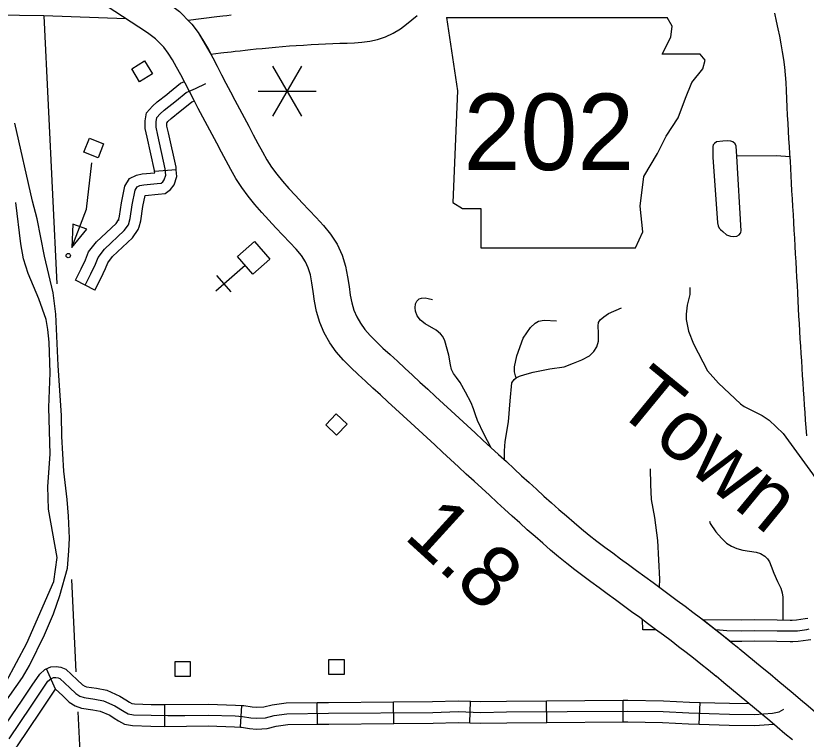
# Model space of a CAD drawing. Extents: x 1370130 to 1380143, y 377636 to 380256.
# Drawn here: x 1378334.6 to 1378563.7, y 378052.1 to 378261.9 of the extents above; entities that cross this region are included whole.
import ezdxf

# ---------------------------------------------------------------- set-up
doc = ezdxf.new("R2010")
doc.units = 0
for name, color, linetype in [('Level 10', 7, 'Continuous'), ('Level 15', 7, 'Continuous'), ('Level 21', 7, 'Continuous'), ('Level 31', 7, 'Continuous'), ('Level 32', 7, 'Continuous'), ('Level 33', 7, 'Continuous'), ('Level 34', 7, 'Continuous'), ('Level 35', 7, 'Continuous'), ('Level 4', 7, 'Continuous'), ('Level 45', 7, 'Continuous'), ('Level 48', 7, 'Continuous'), ('Level 5', 7, 'Continuous'), ('Level 56', 7, 'Continuous'), ('Level 57', 7, 'Continuous'), ('Level 6', 7, 'Continuous')]:
    doc.layers.add(name, color=color, linetype=linetype)

msp = doc.modelspace()

# ---------------------------------------------------------------- linework, layer by layer
at = {"layer": 'Level 10'}
msp.add_line((1378561.65, 378172.62), (1378561.65, 378172.6), dxfattribs=at)
for points in [[(1378554.5, 378262.65), (1378555.02, 378260.29), (1378555.54, 378258.08), (1378556, 378255.94), (1378556.41, 378253.73), (1378556.8, 378251.48), (1378557.15, 378249.24), (1378557.44, 378247.02), (1378557.66, 378244.8), (1378557.81, 378242.52), (1378557.93, 378240.2), (1378558.02, 378237.83), (1378558.11, 378235.43), (1378558.22, 378233.02), (1378558.36, 378230.67), (1378558.5, 378228.4), (1378558.64, 378226.17), (1378558.77, 378223.97), (1378558.91, 378221.81), (1378559.04, 378219.7), (1378559.15, 378217.57), (1378559.27, 378215.47), (1378559.38, 378213.32), (1378559.51, 378211.1), (1378559.64, 378208.84), (1378559.78, 378206.56), (1378559.91, 378204.24), (1378560.05, 378201.98), (1378560.18, 378199.7), (1378560.3, 378197.41), (1378560.43, 378195.11), (1378560.56, 378192.82), (1378560.69, 378190.55), (1378560.82, 378188.26), (1378560.95, 378185.97), (1378561.07, 378183.72), (1378561.2, 378181.46), (1378561.31, 378179.22), (1378561.43, 378177.01), (1378561.54, 378174.81), (1378561.65, 378172.62)], [(1378397, 378262.03), (1378395.75, 378261.89), (1378394.64, 378261.75), (1378393.74, 378261.64), (1378392.9, 378261.56), (1378384.57, 378260.55), (1378385.66, 378259.42), (1378387.43, 378257.03), (1378391.15, 378250.77)], [(1378391.15, 378250.77), (1378394.03, 378251.12), (1378394.89, 378251.2), (1378395.93, 378251.33), (1378397.02, 378251.46), (1378398.24, 378251.61), (1378399.62, 378251.77), (1378401.09, 378251.95), (1378402.63, 378252.11), (1378404.27, 378252.27), (1378406.05, 378252.43), (1378407.96, 378252.61), (1378409.93, 378252.81), (1378411.92, 378253.01), (1378413.9, 378253.2), (1378415.91, 378253.32), (1378418.03, 378253.42), (1378420.19, 378253.52), (1378422.31, 378253.64), (1378424.39, 378253.74), (1378426.49, 378253.82), (1378428.58, 378253.92), (1378430.65, 378253.99), (1378432.75, 378254.08), (1378434.94, 378254.24), (1378437.19, 378254.55), (1378439.48, 378255.06), (1378441.77, 378255.82), (1378444, 378256.85), (1378446.09, 378258.11), (1378447.89, 378259.47), (1378449.45, 378260.74), (1378450.94, 378261.99)], [(1378561.65, 378172.6), (1378561.78, 378170.43), (1378561.9, 378168.24), (1378562.04, 378166.06), (1378562.19, 378163.92), (1378562.33, 378161.8), (1378562.46, 378159.68), (1378562.59, 378157.54), (1378562.73, 378155.42), (1378562.87, 378153.26), (1378563.01, 378151.09), (1378563.16, 378148.94), (1378563.31, 378146.79), (1378563.45, 378144.63), (1378563.59, 378142.44), (1378563.79, 378140.08)]]:
    msp.add_lwpolyline(points, dxfattribs=at)
at = {"layer": 'Level 15'}
for points in [[(1378332.91, 378293.69), (1378334.71, 378292.37), (1378336.92, 378291.04), (1378366.32, 378273.69), (1378378.87, 378265.56), (1378382.04, 378263.09), (1378385.25, 378259.87)], [(1378377.43, 378252.86), (1378375.07, 378255.22), (1378372.78, 378256.99), (1378360.8, 378264.76), (1378331.53, 378282.03)], [(1378385.25, 378259.87), (1378385.66, 378259.42), (1378387.43, 378257.03), (1378389.03, 378254.57), (1378390.42, 378252.1), (1378391.72, 378249.69), (1378393.01, 378247.25), (1378394.27, 378244.81), (1378395.54, 378242.35), (1378396.82, 378239.88), (1378398.12, 378237.39), (1378399.44, 378234.88), (1378400.77, 378232.35), (1378402.12, 378229.83), (1378403.45, 378227.32), (1378404.79, 378224.84), (1378406.12, 378222.43), (1378407.42, 378220.14), (1378408.77, 378218.02), (1378410.28, 378215.98), (1378411.95, 378213.93), (1378413.77, 378211.84), (1378415.68, 378209.72), (1378417.64, 378207.61), (1378419.65, 378205.5), (1378421.72, 378203.34), (1378423.81, 378201.06), (1378425.88, 378198.54), (1378427.77, 378195.66), (1378429.24, 378192.47), (1378430.2, 378189.26), (1378430.79, 378186.21), (1378431.21, 378183.4), (1378431.58, 378180.85), (1378432.02, 378178.59), (1378432.63, 378176.53), (1378433.47, 378174.56), (1378434.51, 378172.69), (1378435.79, 378170.9), (1378437.3, 378169.15), (1378439.06, 378167.38), (1378441.03, 378165.53), (1378443.09, 378163.62), (1378445.22, 378161.67), (1378447.37, 378159.68), (1378449.56, 378157.69), (1378451.76, 378155.66), (1378454.02, 378153.59), (1378456.29, 378151.49), (1378458.57, 378149.38), (1378460.85, 378147.27), (1378463.15, 378145.15), (1378465.46, 378143.02), (1378467.74, 378140.9), (1378470.01, 378138.8), (1378472.27, 378136.72), (1378474.55, 378134.65), (1378476.81, 378132.57), (1378479.03, 378130.52), (1378481.21, 378128.5), (1378483.39, 378126.52), (1378485.54, 378124.55), (1378487.7, 378122.6), (1378489.87, 378120.66), (1378492.05, 378118.73), (1378494.25, 378116.81), (1378496.45, 378114.91), (1378498.64, 378113.06), (1378500.84, 378111.27), (1378503.07, 378109.53), (1378505.35, 378107.8), (1378507.63, 378106.08), (1378509.91, 378104.38), (1378512.22, 378102.69), (1378514.57, 378100.99), (1378516.95, 378099.26), (1378519.34, 378097.52), (1378521.71, 378095.78), (1378524.04, 378094.04), (1378526.33, 378092.32), (1378528.62, 378090.63), (1378530.89, 378088.94), (1378533.13, 378087.25), (1378535.35, 378085.54), (1378537.55, 378083.82), (1378539.78, 378082.05), (1378542.01, 378080.23), (1378544.23, 378078.43)], [(1378537.62, 378070.27), (1378535.38, 378072.09), (1378533.2, 378073.87), (1378531.05, 378075.57), (1378528.9, 378077.25), (1378526.76, 378078.9), (1378524.58, 378080.55), (1378522.36, 378082.21), (1378520.07, 378083.9), (1378517.76, 378085.62), (1378515.46, 378087.34), (1378513.13, 378089.05), (1378510.78, 378090.77), (1378508.41, 378092.49), (1378506.04, 378094.2), (1378503.67, 378095.93), (1378501.33, 378097.68), (1378499.01, 378099.43), (1378496.67, 378101.21), (1378494.3, 378103.05), (1378491.95, 378104.97), (1378489.63, 378106.92), (1378487.36, 378108.88), (1378485.12, 378110.85), (1378482.89, 378112.82), (1378480.68, 378114.79), (1378478.48, 378116.78), (1378476.31, 378118.76), (1378474.12, 378120.76), (1378471.91, 378122.8), (1378469.69, 378124.85), (1378467.46, 378126.9), (1378465.18, 378128.97), (1378462.89, 378131.08), (1378460.6, 378133.2), (1378458.32, 378135.32), (1378456.04, 378137.43), (1378453.73, 378139.55), (1378451.43, 378141.68), (1378449.16, 378143.79), (1378446.91, 378145.86), (1378444.66, 378147.92), (1378442.46, 378149.95), (1378440.28, 378151.95), (1378438.11, 378153.93), (1378435.98, 378155.89), (1378433.86, 378157.85), (1378431.74, 378159.85), (1378429.6, 378162), (1378427.52, 378164.41), (1378425.63, 378167.07), (1378424.02, 378169.94), (1378422.74, 378172.97), (1378421.81, 378176.08), (1378421.22, 378179.1), (1378420.82, 378181.88), (1378420.44, 378184.44), (1378419.99, 378186.74), (1378419.39, 378188.75), (1378418.56, 378190.56), (1378417.4, 378192.32), (1378415.88, 378194.18), (1378414.06, 378196.16), (1378412.06, 378198.25), (1378409.99, 378200.42), (1378407.93, 378202.64), (1378405.91, 378204.88), (1378403.93, 378207.15), (1378401.98, 378209.54), (1378400.12, 378212.07), (1378398.43, 378214.71), (1378396.95, 378217.31), (1378395.57, 378219.82), (1378394.2, 378222.35), (1378392.85, 378224.9), (1378391.49, 378227.44), (1378390.15, 378229.99), (1378388.82, 378232.52), (1378387.51, 378235.03), (1378386.22, 378237.52), (1378384.95, 378239.98), (1378383.7, 378242.39), (1378382.46, 378244.74), (1378381.23, 378247.02), (1378380.04, 378249.14), (1378378.81, 378251.04), (1378377.52, 378252.76), (1378377.43, 378252.86)], [(1378544.27, 378078.4), (1378546.5, 378076.55), (1378548.75, 378074.7), (1378550.99, 378072.84), (1378553.24, 378070.98), (1378555.47, 378069.12), (1378557.71, 378067.25), (1378559.93, 378065.38), (1378562.12, 378063.54), (1378564.3, 378061.7), (1378566.47, 378059.88), (1378568.65, 378058.05), (1378570.76, 378056.2), (1378572.79, 378054.42), (1378574.79, 378052.64), (1378576.84, 378050.75)], [(1378559.72, 378051.84), (1378557.55, 378053.66), (1378555.35, 378055.51), (1378553.16, 378057.36), (1378550.97, 378059.21), (1378548.76, 378061.04), (1378546.53, 378062.9), (1378544.29, 378064.75), (1378542.05, 378066.61), (1378539.82, 378068.46), (1378537.59, 378070.3)]]:
    msp.add_lwpolyline(points, dxfattribs=at)
at = {"layer": 'Level 21'}
for p, q in [((1378459.5, 378261.41), (1378462.69, 378240.1)), ((1378524.87, 378258.93), (1378523.39, 378261.38)), ((1378524.51, 378255.73), (1378524.87, 378258.93)), ((1378522.02, 378250.75), (1378524.51, 378255.73)), ((1378533.04, 378250.75), (1378522.02, 378250.75)), ((1378534.46, 378248.98), (1378533.04, 378250.75)), ((1378533.75, 378246.49), (1378534.46, 378248.98)), ((1378530.55, 378242.58), (1378533.75, 378246.49)), ((1378528.78, 378237.96), (1378530.55, 378242.58)), ((1378462.69, 378240.1), (1378461.27, 378207.77)), ((1378526.64, 378232.28), (1378528.78, 378237.96)), ((1378523.09, 378226.95), (1378526.64, 378232.28)), ((1378520.6, 378221.98), (1378523.09, 378226.95)), ((1378516.7, 378215.23), (1378520.6, 378221.98)), ((1378515.63, 378206.7), (1378516.7, 378215.23)), ((1378461.27, 378207.77), (1378464.11, 378205.99)), ((1378464.11, 378205.99), (1378469.44, 378205.99)), ((1378469.44, 378205.99), (1378469.44, 378194.62)), ((1378516.34, 378199.24), (1378515.63, 378206.7)), ((1378514.21, 378194.62), (1378516.34, 378199.24)), ((1378469.44, 378194.62), (1378514.21, 378194.62))]:
    msp.add_line(p, q, dxfattribs=at)
msp.add_lwpolyline([(1378459.5, 378261.41), (1378523.39, 378261.38)], dxfattribs=at)
at = {"layer": 'Level 31'}
msp.add_line((1378541.8, 378080.4), (1378542.01, 378080.23), dxfattribs=at)
for points in [[(1378542.01, 378080.23), (1378533.7, 378086.81), (1378545.03, 378086.66), (1378548.83, 378086.78), (1378555.35, 378086.66), (1378559.07, 378086.6), (1378559.65, 378086.62)], [(1378559.65, 378086.62), (1378560.88, 378086.65), (1378563.42, 378087.04), (1378564.18, 378087.15)], [(1378537.58, 378083.89), (1378540.68, 378083.57), (1378545.06, 378083.51), (1378548.85, 378083.63), (1378555.3, 378083.51), (1378559.09, 378083.45), (1378561.16, 378083.51), (1378563.88, 378083.92), (1378564.63, 378084.03)], [(1378559.83, 378080.32), (1378559.11, 378080.3), (1378555.25, 378080.36), (1378548.87, 378080.48), (1378545.09, 378080.36), (1378541.8, 378080.4)], [(1378565.07, 378080.91), (1378564.34, 378080.81), (1378561.44, 378080.37), (1378559.83, 378080.32)]]:
    msp.add_lwpolyline(points, dxfattribs=at)
at = {"layer": 'Level 32'}
for p, q in [((1378444.19, 378056.59), (1378444.14, 378062.89)), ((1378466.21, 378056.81), (1378466.46, 378063.1)), ((1378488.53, 378056.9), (1378488.48, 378063.2)), ((1378510.7, 378057.06), (1378510.66, 378063.36)), ((1378377.83, 378055.79), (1378377.77, 378062.09)), ((1378399.78, 378055.57), (1378400.15, 378061.85)), ((1378422.02, 378056.4), (1378421.96, 378062.69)), ((1378532.74, 378056.46), (1378532.95, 378062.75))]:
    msp.add_line(p, q, dxfattribs=at)
for points in [[(1378421.96, 378062.69), (1378425.27, 378062.73), (1378444.14, 378062.89)], [(1378444.14, 378062.89), (1378455.42, 378062.98), (1378462.88, 378063.24), (1378466.46, 378063.1)], [(1378466.46, 378063.1), (1378469.4, 378062.99), (1378476.85, 378063.11), (1378488.48, 378063.2)], [(1378488.48, 378063.2), (1378510.66, 378063.36)], [(1378510.66, 378063.36), (1378512.04, 378063.37), (1378522.32, 378063.24), (1378529.87, 378062.85), (1378532.95, 378062.75)], [(1378377.77, 378062.09), (1378390.44, 378062.22), (1378398.32, 378061.96), (1378400.15, 378061.85)], [(1378377.8, 378058.94), (1378390.41, 378059.07), (1378398.18, 378058.82), (1378400.34, 378058.69), (1378402.76, 378058.31), (1378404.42, 378058.18), (1378406.96, 378058.31), (1378409.51, 378058.94), (1378413.2, 378059.45), (1378425.3, 378059.58), (1378455.49, 378059.83), (1378462.87, 378060.09), (1378469.37, 378059.83), (1378476.88, 378059.96), (1378512.03, 378060.22), (1378522.22, 378060.09), (1378529.74, 378059.71), (1378541.45, 378059.32), (1378548.71, 378059.2), (1378553.94, 378059.58), (1378555.85, 378059.96), (1378557.27, 378060.76)], [(1378400.15, 378061.85), (1378400.68, 378061.82), (1378403.13, 378061.44), (1378404.46, 378061.33), (1378406.5, 378061.44), (1378408.91, 378062.04), (1378412.97, 378062.6), (1378421.96, 378062.69)], [(1378532.95, 378062.75), (1378541.53, 378062.47), (1378547.16, 378062.38)], [(1378399.78, 378055.57), (1378400, 378055.55), (1378402.39, 378055.17), (1378404.37, 378055.02), (1378407.43, 378055.17), (1378410.11, 378055.85), (1378413.44, 378056.3), (1378422.02, 378056.4)], [(1378422.02, 378056.4), (1378425.33, 378056.43), (1378444.19, 378056.59)], [(1378444.19, 378056.59), (1378455.55, 378056.69), (1378462.87, 378056.94), (1378466.21, 378056.81)], [(1378466.21, 378056.81), (1378469.33, 378056.68), (1378476.92, 378056.81), (1378488.53, 378056.9)], [(1378488.53, 378056.9), (1378510.7, 378057.06)], [(1378510.7, 378057.06), (1378512.03, 378057.07), (1378522.12, 378056.94), (1378529.61, 378056.56), (1378532.74, 378056.46)], [(1378532.74, 378056.46), (1378541.38, 378056.18), (1378548.8, 378056.05), (1378554.24, 378056.44)], [(1378377.83, 378055.79), (1378390.37, 378055.92), (1378398.03, 378055.67), (1378399.78, 378055.57)]]:
    msp.add_lwpolyline(points, dxfattribs=at)
at = {"layer": 'Level 33'}
for points in [[(1378543.59, 378221.17), (1378543.42, 378224.07), (1378543.1, 378224.74), (1378542.47, 378225.31), (1378541.84, 378225.5), (1378541.03, 378225.62), (1378539.52, 378225.56), (1378537.77, 378225.31), (1378537.14, 378224.87), (1378536.76, 378224.43), (1378536.7, 378223.99), (1378536.64, 378223.24), (1378536.7, 378220.92), (1378538.02, 378201.85), (1378538.24, 378200.97), (1378538.52, 378200.34), (1378538.89, 378199.92), (1378539.58, 378199.28), (1378540.65, 378198.4), (1378541.78, 378197.96), (1378542.66, 378197.83), (1378543.6, 378197.96), (1378544.29, 378198.34), (1378544.66, 378198.84), (1378544.78, 378199.15), (1378544.86, 378199.53), (1378543.59, 378221.17)], [(1378558.96, 378221.03), (1378555.13, 378221.23), (1378543.59, 378221.17)]]:
    msp.add_lwpolyline(points, dxfattribs=at)
at = {"layer": 'Level 34'}
for points in [[(1378472.38, 378136.61), (1378470.26, 378140.61), (1378468.41, 378144.46), (1378467.87, 378146.16), (1378467.33, 378147.93), (1378466.64, 378149.63), (1378464.95, 378152.71), (1378463.41, 378155.56), (1378462.33, 378156.95), (1378461.48, 378158.18), (1378460.94, 378159.26), (1378460.63, 378160.64), (1378460.17, 378163.49), (1378459.02, 378167.58), (1378458.4, 378168.89), (1378457.71, 378169.66), (1378456.47, 378170.66), (1378453.32, 378172.51), (1378451.93, 378173.59), (1378450.93, 378174.9), (1378450.47, 378176.21), (1378450.39, 378177.21), (1378450.47, 378178.37), (1378450.85, 378179.14), (1378451.55, 378179.75), (1378452.24, 378179.98), (1378453.24, 378180.06), (1378454.16, 378179.91), (1378455.4, 378179.6)], [(1378476.27, 378133.17), (1378476.27, 378135.68), (1378476.5, 378138.45), (1378477.42, 378144.08), (1378477.96, 378150.24), (1378478.35, 378155.4), (1378479.04, 378156.41), (1378479.65, 378156.87), (1378480.58, 378157.33), (1378482.2, 378157.87), (1378484.58, 378158.49), (1378489.44, 378159.49), (1378493.59, 378160.1), (1378496.29, 378161.11), (1378498.68, 378162.11), (1378500.91, 378163.26), (1378502.14, 378164.5), (1378503.07, 378165.88), (1378503.53, 378167.5), (1378503.53, 378169.81), (1378503.45, 378171.97), (1378503.53, 378172.97), (1378503.99, 378173.67), (1378505.07, 378174.59), (1378506.45, 378175.52), (1378510.15, 378177.21)], [(1378479.65, 378156.87), (1378479.42, 378157.48), (1378479.19, 378158.64), (1378479.19, 378160.1), (1378479.89, 378163.26), (1378481.66, 378168.35), (1378483.81, 378171.51), (1378485.12, 378172.74), (1378486.12, 378173.28), (1378487.74, 378173.59), (1378491.36, 378173.43)], [(1378521.17, 378096.18), (1378521.28, 378098.48), (1378520.72, 378109.66), (1378519.85, 378116.38), (1378518.86, 378121.6), (1378518.73, 378125.91), (1378518.57, 378130.44)], [(1378535.67, 378115.35), (1378535.92, 378114.67), (1378537.52, 378112.26), (1378539.19, 378110.37), (1378540.64, 378108.95), (1378542.06, 378108.06), (1378543.59, 378107.35), (1378545.4, 378106.86), (1378547.32, 378106.61), (1378549.27, 378106.32), (1378550.48, 378105.9), (1378551.72, 378105.11), (1378552.54, 378104.4), (1378553.11, 378103.51), (1378553.54, 378102.24), (1378554.35, 378100.21), (1378555.38, 378097.83), (1378556.38, 378095.84), (1378556.73, 378094.52), (1378556.91, 378093.28), (1378556.95, 378091.75), (1378556.95, 378086.63)]]:
    msp.add_lwpolyline(points, dxfattribs=at)
at = {"layer": 'Level 35'}
for points in [[(1378328.41, 378058.51), (1378336.52, 378069.96), (1378338.55, 378073.45), (1378342.96, 378082.38), (1378345.58, 378088.46), (1378347.41, 378093.72), (1378349.57, 378101.67), (1378350.01, 378106.74), (1378350.15, 378110.36), (1378349.89, 378116.75), (1378349.54, 378121.58), (1378348.49, 378129.81), (1378347.95, 378139.82), (1378347.82, 378145.92), (1378346.9, 378160.46), (1378346.21, 378175.31), (1378345.41, 378181.56), (1378342.96, 378192.16), (1378340.8, 378202.98), (1378339.43, 378208.17), (1378334.34, 378230.79)], [(1378331.78, 378068.68), (1378337.79, 378079.92), (1378345.6, 378097.85), (1378346.6, 378104.77), (1378344.12, 378118.78), (1378343.94, 378125.34), (1378344.55, 378134.74), (1378344.19, 378148.24), (1378344.58, 378158.35), (1378344.31, 378167.19), (1378343.9, 378170.88), (1378343.38, 378173.78), (1378341.32, 378179.79), (1378338.22, 378187.18), (1378336.83, 378191.4), (1378336.11, 378195.72), (1378334.6, 378207.77)], [(1378530, 378183.12), (1378530, 378181.02), (1378529.22, 378177.97), (1378528.9, 378175.31), (1378528.97, 378173.8), (1378529.59, 378170.4), (1378531.05, 378166.73), (1378535.09, 378158.9), (1378538.32, 378155.31), (1378544.68, 378149.34), (1378545.79, 378148.52), (1378550.94, 378145.97), (1378552.99, 378144.63), (1378557.08, 378140.71), (1378565.57, 378129.02), (1378570.05, 378122.3), (1378577.07, 378110.74), (1378579.28, 378105.82), (1378580.76, 378103.2), (1378584.44, 378098.48), (1378587.33, 378095.38), (1378590.55, 378092.59), (1378593.87, 378090.72), (1378594.23, 378090.58)]]:
    msp.add_lwpolyline(points, dxfattribs=at)
at = {"layer": 'Level 4'}
msp.add_lwpolyline([(1378366.54, 378261.04), (1378342.74, 378261.84), (1378335.69, 378261.94), (1378316.08, 378262.23)], dxfattribs=at)
at = {"layer": 'Level 45'}
for p, q in [((1378381.12, 378217.2), (1378374.84, 378216.74)), ((1378357.52, 378182.35), (1378351.91, 378185.22)), ((1378346.16, 378066.54), (1378343.53, 378072.49))]:
    msp.add_line(p, q, dxfattribs=at)
for points in [[(1378354.72, 378183.78), (1378356.4, 378187.07), (1378357.73, 378189.87), (1378358.49, 378191.83), (1378360.31, 378194.21), (1378366.05, 378199.6), (1378367.24, 378201.28), (1378367.8, 378203.1), (1378368.36, 378207.09), (1378369.2, 378211.36), (1378369.76, 378212.27), (1378370.59, 378212.69), (1378371.71, 378212.9), (1378375.56, 378213.25), (1378376.75, 378213.39), (1378377.24, 378213.74), (1378377.66, 378214.3), (1378378.08, 378215.63), (1378377.94, 378217.52), (1378375.77, 378227.31), (1378375.28, 378229.55), (1378375.28, 378231.16), (1378375.49, 378232.35), (1378376.47, 378233.47), (1378377.66, 378234.52), (1378381.16, 378237.32), (1378384.02, 378239.63), (1378386.68, 378240.82), (1378389.67, 378242.29)], [(1378378.35, 378239.11), (1378379.18, 378239.78), (1378382.37, 378242.34), (1378383.47, 378242.83)], [(1378374.84, 378216.74), (1378374.81, 378217.06), (1378372.69, 378226.64), (1378372.13, 378229.21), (1378372.13, 378231.44), (1378372.54, 378233.76), (1378374.23, 378235.7), (1378375.63, 378236.93), (1378378.35, 378239.11)], [(1378382.29, 378234.19), (1378383.13, 378234.86), (1378385.68, 378236.92), (1378386.37, 378237.23)], [(1378381.12, 378217.2), (1378381.06, 378217.97), (1378378.85, 378227.99), (1378378.43, 378229.89), (1378378.43, 378230.89), (1378378.44, 378230.94), (1378378.71, 378231.24), (1378379.69, 378232.11), (1378382.29, 378234.19)], [(1378364.33, 378202.55), (1378364.71, 378203.79), (1378365.25, 378207.61), (1378366.21, 378212.52), (1378367.54, 378214.68), (1378369.58, 378215.7), (1378371.28, 378216.02), (1378374.87, 378216.35), (1378374.84, 378216.74)], [(1378370.35, 378200.7), (1378370.88, 378202.41), (1378371.46, 378206.57), (1378372.09, 378209.76), (1378372.15, 378209.77), (1378375.89, 378210.11), (1378377.92, 378210.35), (1378379.47, 378211.46), (1378380.5, 378212.84), (1378381.26, 378215.26), (1378381.12, 378217.2)], [(1378351.91, 378185.22), (1378353.57, 378188.47), (1378354.83, 378191.13), (1378355.72, 378193.39), (1378357.97, 378196.33), (1378363.66, 378201.68), (1378364.37, 378202.69), (1378364.33, 378202.55)], [(1378357.52, 378182.35), (1378359.22, 378185.68), (1378360.62, 378188.62), (1378361.27, 378190.27), (1378362.66, 378192.09), (1378368.44, 378197.52), (1378370.1, 378199.87), (1378370.35, 378200.7)], [(1378330.28, 378054.26), (1378336.41, 378063.36), (1378339.34, 378067.78), (1378341.55, 378070.95), (1378342.98, 378072.25), (1378344.11, 378072.75)], [(1378344.11, 378072.75), (1378344.77, 378073.04), (1378346.3, 378073.15), (1378347.62, 378072.99), (1378349.12, 378072.41), (1378352.43, 378069.29), (1378353.99, 378067.81), (1378354.61, 378067.41), (1378355.13, 378067.22), (1378358.02, 378066.83), (1378360.97, 378066.24), (1378364.77, 378064.58), (1378366.48, 378063.51)], [(1378332.69, 378052.19), (1378339.03, 378061.61), (1378341.95, 378066.01), (1378343.93, 378068.86), (1378344.72, 378069.58), (1378345.54, 378069.94), (1378346.23, 378069.98), (1378346.85, 378069.91), (1378347.4, 378069.69), (1378350.26, 378067), (1378352.03, 378065.32), (1378353.21, 378064.56), (1378354.38, 378064.14), (1378357.5, 378063.72), (1378360.02, 378063.22), (1378363.3, 378061.79), (1378365.99, 378060.1), (1378367.17, 378059.43), (1378368.76, 378059.18), (1378373.81, 378059.01), (1378383.47, 378058.82)], [(1378334.61, 378049.68), (1378335.09, 378050.13), (1378341.65, 378059.86), (1378344.55, 378064.24), (1378346.16, 378066.54)], [(1378346.16, 378066.54), (1378348.1, 378064.72), (1378350.07, 378062.83), (1378351.81, 378061.72), (1378353.63, 378061.06), (1378356.97, 378060.61), (1378359.07, 378060.19), (1378361.82, 378058.99), (1378363.14, 378058.17)], [(1378366.48, 378063.51), (1378367.61, 378062.81), (1378368.23, 378062.45), (1378369.06, 378062.32), (1378373.89, 378062.16), (1378377.77, 378062.09)], [(1378363.14, 378058.17), (1378364.37, 378057.4), (1378366.1, 378056.41), (1378368.46, 378056.04), (1378373.73, 378055.86), (1378377.83, 378055.79)]]:
    msp.add_lwpolyline(points, dxfattribs=at)
at = {"layer": 'Level 48'}
for p, q in [((1378417.45, 378247.31), (1378409.05, 378232.76)), ((1378409.05, 378247.31), (1378417.45, 378232.76)), ((1378404.85, 378240.03), (1378421.65, 378240.03))]:
    msp.add_line(p, q, dxfattribs=at)
at = {"layer": 'Level 5'}
for points in [[(1378342.74, 378261.84), (1378346.54, 378184.19)], [(1378350.74, 378098.37), (1378352.05, 378071.56)], [(1378352.62, 378060), (1378355.36, 378003.92)]]:
    msp.add_lwpolyline(points, dxfattribs=at)
at = {"layer": 'Level 56'}
for points in [[(1378374.22, 378245.08), (1378370.51, 378242.78), (1378368.2, 378246.51), (1378371.92, 378248.81)], [(1378360.04, 378224.78), (1378358.45, 378220.71), (1378354.37, 378222.31), (1378355.96, 378226.38)], [(1378355.17, 378199.96), (1378351.16, 378201.48), (1378350.88, 378194.71)], [(1378427.62, 378140.24), (1378424.47, 378143.28), (1378427.52, 378146.43), (1378430.66, 378143.4)], [(1378380.79, 378070.21), (1378380.79, 378074.58), (1378385.17, 378074.58), (1378385.17, 378070.21)], [(1378425.37, 378070.8), (1378425.37, 378075.17), (1378429.75, 378075.17), (1378429.75, 378070.8)]]:
    msp.add_lwpolyline(points, close=True, dxfattribs=at)
msp.add_lwpolyline([(1378350.88, 378194.71), (1378355.1, 378205.8), (1378356.68, 378219.26)], dxfattribs=at)
msp.add_circle((1378349.82, 378192.34), 0.63, dxfattribs=at)
at = {"layer": 'Level 57'}
for p, q in [((1378392.59, 378182.08), (1378401.08, 378189.55)), ((1378397.04, 378181.8), (1378392.87, 378186.53))]:
    msp.add_line(p, q, dxfattribs=at)
msp.add_lwpolyline([(1378408.25, 378191.32), (1378403.33, 378186.99), (1378398.84, 378192.09), (1378403.76, 378196.42)], close=True, dxfattribs=at)
at = {"layer": 'Level 6'}
msp.add_lwpolyline([(1378519.91, 378083.79), (1378516.42, 378083.77), (1378516.25, 378086.72)], dxfattribs=at)

# ---------------------------------------------------------------- texts
at = {"layer": 'Level 21'}
msp.add_text('202', height=22.176, dxfattribs=at).set_placement((1378464.41, 378217.14))
at = {"layer": 'Level 35'}
msp.add_text('Town', height=17.741, rotation=320.6063, dxfattribs=at).set_placement((1378507.73, 378147.91))
at = {"layer": 'Level 48'}
msp.add_text('1.8', height=17.741, rotation=317.7001, dxfattribs=at).set_placement((1378446.76, 378110.58))

doc.saveas('drawing.dxf')
